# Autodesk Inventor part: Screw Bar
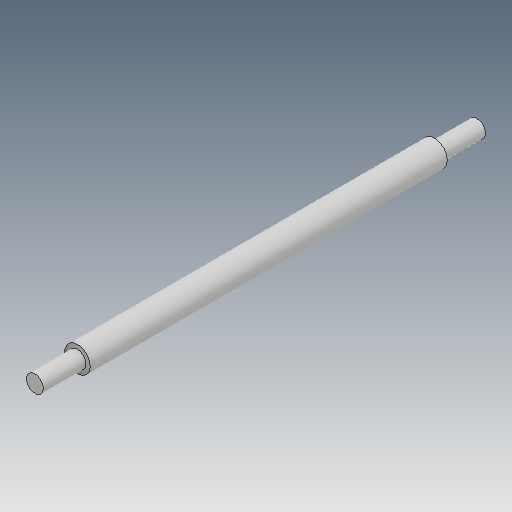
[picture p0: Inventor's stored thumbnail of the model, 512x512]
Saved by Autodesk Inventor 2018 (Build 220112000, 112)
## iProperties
Created: 2016-03
Part Number: Screw Bar
Material: Generic
Document SubType Name: Modeling
Designer: Sandeep
Density: 1 g/cm^3
Appearance: Default
Mass: 2.62637 g
Surface Area: 18.9124 cm^2
Volume: 2.62637 cm^3
Author: Sandeep
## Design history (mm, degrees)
sketch "Sketch1"
  geometry: L1 (-104, 2)-(-94, 2); L2 (-94, 2)-(-94, 3); L3 (-94, 3)-(-10, 3); L4 (-10, 3)-(-10, 2); L5 (-10, 2)-(0, 2); L6 (0, 2)-(0, 0); L7 (-104, 2)-(-104, 0); L8 (-104, 0)-(0, 0); L9 (0, 0)-(21.698, 0)
  constraints: 18 end point, 4 perpendicular, 3 horizontal, 2 point on line, 1 vertical
  dimensions: "d0" = 4 diameter of L5 L9; "d1" = 6 diameter of L3 L9; "d2" = 10 distance of L4.end L5.end; "d3" = 10 distance of L1.start L1.end; "d4" = 104 distance between parallel lines of L7 L6
revolve "Revolution1" sketch "Sketch1" stored, may be unused: angle "d5" = 90 deg
body "Solid1"
